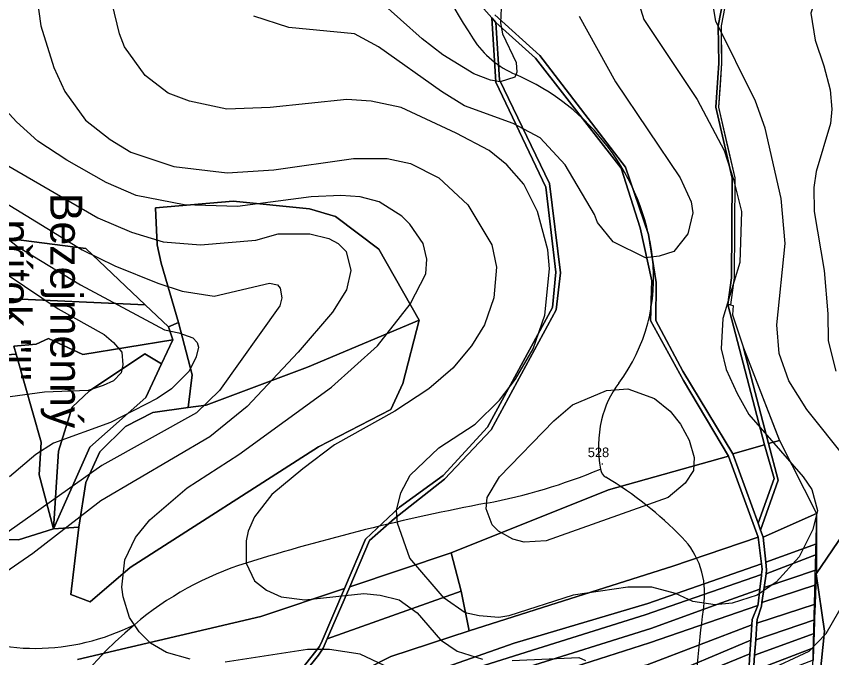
# Model space of a CAD drawing. Extents: x -510989 to -501240, y -1184665 to -1176098.
# Drawn here: x -509271 to -508760, y -1177973 to -1177572 of the extents above; entities that cross this region are included whole.
import ezdxf

# ---------------------------------------------------------------- set-up
doc = ezdxf.new("R2010")
doc.units = 0
for name, color, linetype in [('lesni_pozemek', 7, 'Continuous'), ('NAVRH_rozvodnice', 7, 'Continuous'), ('ostatni_plocha_x_ostatni_komunikace', 7, 'Continuous'), ('popis', 7, 'Continuous'), ('STAV_povodi', 7, 'Continuous'), ('STAV_USES', 7, 'Continuous'), ('vrstevnice_01', 7, 'Continuous'), ('vrstevnice_02', 7, 'Continuous'), ('vrstevnice_05', 7, 'Continuous')]:
    doc.layers.add(name, color=color, linetype=linetype)

msp = doc.modelspace()

# ---------------------------------------------------------------- linework, layer by layer
at = {"layer": 'lesni_pozemek'}
for points in [[(-508825.95, -1177550.04), (-508831.28, -1177577.88), (-508830.98, -1177601.29), (-508832.87, -1177628.86), (-508822.71, -1177673.28), (-508823.1, -1177735.5), (-508825.26, -1177752.3), (-508802.43, -1177839.98), (-508822.23, -1177845.65), (-508853.52, -1177793.89), (-508870.46, -1177762.32), (-508870.1, -1177738.53), (-508874.93, -1177708.45), (-508889.31, -1177666.35), (-508942.96, -1177596.56), (-508971.1, -1177571.13)], [(-508986.2, -1177557.99), (-508973.14, -1177572.9), (-508970.58, -1177613.22), (-508939.21, -1177678.9), (-508933.1, -1177731.98), (-508935.17, -1177754.12), (-508975.79, -1177829.02), (-509003.54, -1177859.28), (-509030.8, -1177879.01), (-509052.19, -1177899.03), (-509065.4, -1177929.91), (-509117.63, -1177947.35), (-509232.41, -1177974.31)], [(-509368.09, -1177896.51), (-509269.43, -1177899.49), (-509247.48, -1177892.47), (-509231.55, -1177891.53), (-509236.62, -1177933.69), (-509224.49, -1177938.17), (-509199.53, -1177916.69), (-509081.59, -1177841.26), (-509036.26, -1177817.95), (-509028.86, -1177801.63), (-509018.6, -1177762.06), (-509043.74, -1177717.55), (-509070.88, -1177697.22), (-509087.17, -1177692.47), (-509134.99, -1177687.6), (-509183.61, -1177691.74), (-509182.52, -1177714.98), (-509180.02, -1177726.39), (-509169.13, -1177763.48), (-509175.54, -1177766.22), (-509190.09, -1177752.44), (-509227.24, -1177717.25), (-509274.16, -1177711.28)], [(-509232.41, -1177974.31), (-509117.63, -1177947.35), (-509065.4, -1177929.91), (-509079.35, -1177962.52), (-509080.85, -1177966.05), (-509100.39, -1177990.69)]]:
    msp.add_lwpolyline(points, dxfattribs=at)
for points in [[(-508945.69, -1177598.23), (-508892.18, -1177666.97), (-508880.3, -1177704.25), (-508872.94, -1177737.37), (-508873.65, -1177762.28), (-508853.05, -1177799.88), (-508825.01, -1177847.03), (-508900.12, -1177868.11), (-508998.54, -1177907.58), (-509062.05, -1177928.79), (-509049.58, -1177899.86), (-509033.96, -1177886.15), (-509002.63, -1177861.51), (-508973.4, -1177830.64), (-508932.81, -1177755.64), (-508930.17, -1177732.36), (-508936.97, -1177676.59), (-508968.33, -1177611.84), (-508970.48, -1177575.95)], [(-509183.61, -1177691.74), (-509134.99, -1177687.6), (-509087.17, -1177692.47), (-509070.88, -1177697.22), (-509043.74, -1177717.55), (-509018.6, -1177762.06), (-509088.47, -1177791.42), (-509151.8, -1177815.23), (-509163.19, -1177816.64), (-509160.59, -1177796.3), (-509169.13, -1177763.48), (-509180.02, -1177726.39), (-509182.52, -1177714.98)], [(-509336.68, -1177703.21), (-509323.78, -1177703.76), (-509296.4, -1177708.45), (-509274.16, -1177711.28), (-509227.24, -1177717.25), (-509190.09, -1177752.44), (-509281.88, -1177748.35), (-509310.14, -1177743.6), (-509369.65, -1177715.71), (-509371.53, -1177713.69), (-509381.06, -1177712.35), (-509377.83, -1177696.33)], [(-509395.4, -1177703.59), (-509381.06, -1177712.35), (-509371.53, -1177713.69), (-509369.65, -1177715.71), (-509346.15, -1177740.87), (-509334.77, -1177760.26), (-509334.42, -1177770.52), (-509317.21, -1177786.73), (-509270.78, -1177783.38), (-509255.22, -1177838.34), (-509256.51, -1177858.83), (-509247.48, -1177892.47), (-509269.43, -1177899.49), (-509368.09, -1177896.51), (-509389.83, -1177840.04), (-509406.67, -1177783.18), (-509415.55, -1177773.21), (-509424.26, -1177763.43), (-509459.96, -1177714.28), (-509460.46, -1177711.83), (-509428.68, -1177701.8)], [(-509369.65, -1177715.71), (-509310.14, -1177743.6), (-509281.88, -1177748.35), (-509190.09, -1177752.44), (-509175.54, -1177766.22), (-509172.83, -1177774.43), (-509229.18, -1177783.49), (-509250.51, -1177773.62), (-509258.36, -1177777.12), (-509272.24, -1177778.21), (-509270.78, -1177783.38), (-509317.21, -1177786.73), (-509334.42, -1177770.52), (-509334.77, -1177760.26), (-509346.15, -1177740.87)], [(-509175.54, -1177766.22), (-509169.13, -1177763.48), (-509160.59, -1177796.3), (-509163.19, -1177816.64), (-509185.34, -1177819.89), (-509202.38, -1177828.64), (-509218.48, -1177844.48), (-509227.2, -1177863.48), (-509231.55, -1177891.53), (-509247.48, -1177892.47), (-509224.81, -1177841.41), (-509189.71, -1177810.48), (-509179.79, -1177789.28), (-509172.83, -1177774.43)], [(-509018.6, -1177762.06), (-509028.86, -1177801.63), (-509036.26, -1177817.95), (-509081.59, -1177841.26), (-509199.53, -1177916.69), (-509224.49, -1177938.17), (-509236.62, -1177933.69), (-509231.55, -1177891.53), (-509227.2, -1177863.48), (-509218.48, -1177844.48), (-509202.38, -1177828.64), (-509185.34, -1177819.89), (-509163.19, -1177816.64), (-509151.8, -1177815.23), (-509088.47, -1177791.42)], [(-509250.51, -1177773.62), (-509229.18, -1177783.49), (-509172.83, -1177774.43), (-509179.79, -1177789.28), (-509190.31, -1177783.11), (-509224.99, -1177806.15), (-509235.83, -1177816.55), (-509244.28, -1177844), (-509247.48, -1177892.47), (-509256.51, -1177858.83), (-509255.22, -1177838.34), (-509270.78, -1177783.38), (-509272.24, -1177778.21), (-509258.36, -1177777.12)], [(-509179.79, -1177789.28), (-509189.71, -1177810.48), (-509224.81, -1177841.41), (-509247.48, -1177892.47), (-509244.28, -1177844), (-509235.83, -1177816.55), (-509224.99, -1177806.15), (-509190.31, -1177783.11)], [(-508793.21, -1177836.93), (-508793.07, -1177837.3), (-508799.81, -1177839.23), (-508815.51, -1177779.25)], [(-508822.23, -1177845.65), (-508802.43, -1177839.98), (-508796.34, -1177861.15), (-508806.32, -1177889.11)], [(-508799.81, -1177839.23), (-508793.07, -1177837.3), (-508769.77, -1177882.88), (-508803.19, -1177897.68), (-508804.78, -1177893.32), (-508793.85, -1177862.2)], [(-508900.12, -1177868.11), (-508825.01, -1177847.03), (-508806.28, -1177897.85), (-508859.67, -1177916), (-508936.67, -1177940.28), (-508987.15, -1177956.38), (-508992.36, -1177931.55), (-508998.54, -1177907.58)], [(-508769.77, -1177882.88), (-508769.75, -1177901.97), (-508801.54, -1177913.34), (-508803.19, -1177897.68)], [(-508806.28, -1177897.85), (-508804.15, -1177914.52), (-508875.38, -1177939.19), (-508959.16, -1177964.08), (-509074.82, -1178004.67), (-509111.08, -1178010.09), (-509105.44, -1178004.14), (-509100.17, -1177995.27), (-509069.33, -1177989.03), (-509036.27, -1177972.5), (-508987.15, -1177956.38), (-508936.67, -1177940.28), (-508859.67, -1177916)], [(-508769.74, -1177908.54), (-508801.39, -1177920.77), (-508801.03, -1177918.21), (-508801.54, -1177913.34), (-508769.75, -1177901.97)], [(-509062.05, -1177928.79), (-508998.54, -1177907.58), (-508992.36, -1177931.55), (-509076.08, -1177961.36)], [(-508769.73, -1177915.4), (-508769.84, -1177918.3), (-508802.6, -1177929.23), (-508801.39, -1177920.77), (-508769.74, -1177908.54)], [(-508804.15, -1177914.52), (-508803.74, -1177917.73), (-508804.17, -1177921.18), (-508877.09, -1177946.41), (-508944.29, -1177967.4), (-508996.73, -1177983.78), (-509067.03, -1178009.67), (-509122.64, -1178022.27), (-509111.08, -1178010.09), (-509074.82, -1178004.67), (-508959.16, -1177964.08), (-508875.38, -1177939.19)], [(-508804.17, -1177921.18), (-508804.25, -1177921.87), (-508805.25, -1177930.11), (-508805.26, -1177930.19), (-508829.2, -1177938.88), (-508873.52, -1177954.94), (-508953.47, -1177979.96), (-508997.15, -1177993.63), (-509067.19, -1178019.01), (-509132.5, -1178033.97), (-509122.64, -1178022.27), (-509067.03, -1178009.67), (-508996.73, -1177983.78), (-508944.29, -1177967.4), (-508877.09, -1177946.41)], [(-508770.19, -1177927.48), (-508803.95, -1177938.64), (-508802.6, -1177929.23), (-508769.84, -1177918.3)], [(-508805.26, -1177930.19), (-508806.39, -1177939.45), (-508806.53, -1177940.6), (-508874.28, -1177963.93), (-508947.4, -1177987.17), (-509067.75, -1178029.97), (-509140.79, -1178046.49), (-509132.5, -1178033.97), (-509067.19, -1178019.01), (-508997.15, -1177993.63), (-508953.47, -1177979.96), (-508873.52, -1177954.94), (-508829.2, -1177938.88)], [(-508992.36, -1177931.55), (-508987.15, -1177956.38), (-509036.27, -1177972.5), (-509069.33, -1177989.03), (-509100.17, -1177995.27), (-509098.68, -1177992.77), (-509081.5, -1177971.66), (-509078.57, -1177967.14), (-509076.08, -1177961.36)], [(-508770.19, -1177927.48), (-508770.66, -1177939.7), (-508807.11, -1177951.6), (-508806.94, -1177949.31), (-508804.28, -1177940.97), (-508803.95, -1177938.64)], [(-508806.53, -1177940.6), (-508810.19, -1177949.32), (-508810.39, -1177952.5), (-508875.87, -1177977.59), (-508905.22, -1177985.17), (-508948.08, -1177999.95), (-508972.48, -1178008.36), (-509011.93, -1178021.39), (-509049.63, -1178034.31), (-509091.67, -1178048.05), (-509121.92, -1178053.59), (-509150.14, -1178060.6), (-509140.79, -1178046.49), (-509067.75, -1178029.97), (-508947.4, -1177987.17), (-508874.28, -1177963.93)], [(-508771, -1177948.51), (-508771.03, -1177949.49), (-508807.88, -1177962.08), (-508807.11, -1177951.6), (-508770.66, -1177939.7)], [(-508810.39, -1177952.5), (-508811, -1177962.29), (-508871.29, -1177987.63), (-508957.53, -1178018.19), (-509020.48, -1178039.36), (-509063.78, -1178053.18), (-509104.98, -1178061.47), (-509106.84, -1178061.13), (-509113.54, -1178057.24), (-509158.14, -1178073.02), (-509150.14, -1178060.6), (-509121.92, -1178053.59), (-509091.67, -1178048.05), (-509049.63, -1178034.31), (-509011.93, -1178021.39), (-508972.48, -1178008.36), (-508948.08, -1177999.95), (-508905.22, -1177985.17), (-508875.87, -1177977.59)], [(-508771.33, -1177958.1), (-508808.59, -1177971.67), (-508807.88, -1177962.08), (-508771.03, -1177949.49)], [(-508811, -1177962.29), (-508811.52, -1177970.69), (-508862.51, -1177991.57), (-508933.29, -1178017.67), (-508989.67, -1178037.82), (-509064.49, -1178061.9), (-509103.58, -1178069.74), (-509104.98, -1178061.47), (-509063.78, -1178053.18), (-509020.48, -1178039.36), (-508957.53, -1178018.19), (-508871.29, -1177987.63)], [(-508771.65, -1177966.97), (-508809.31, -1177981.38), (-508808.59, -1177971.67), (-508771.33, -1177958.1)], [(-508771.93, -1177974.62), (-508810.53, -1177989.45), (-508809.81, -1177988.13), (-508809.31, -1177981.38), (-508771.65, -1177966.97)], [(-508811.52, -1177970.69), (-508812.21, -1177981.68), (-508848.22, -1177996), (-508909.09, -1178019.27), (-508986.62, -1178044.82), (-509029.02, -1178058.79), (-509070.47, -1178071.64), (-509097.96, -1178076.43), (-509103.58, -1178069.74), (-509064.49, -1178061.9), (-508989.67, -1178037.82), (-508933.29, -1178017.67), (-508862.51, -1177991.57)]]:
    msp.add_lwpolyline(points, close=True, dxfattribs=at)
at = {"layer": 'NAVRH_rozvodnice'}
for centre, radius, start, end in [((-508669.12, -1177378.82), 377.62, 199.0374, 213.2975), ((-508934.26, -1177552.97), 60.41, 213.2975, 246.8138), ((-509014.23, -1177739.68), 142.71, 6.916, 66.8138), ((-508981.45, -1177735.71), 109.69, 323.2339, 6.916), ((-508843.49, -1177838.79), 62.53, 143.2339, 166.7507), ((-508831.15, -1177841.7), 75.21, 166.7507, 190.3863), ((-509042.95, -1177523.22), 359.5, 280.6777, 292.5435), ((-508897.85, -1177853.92), 7.4, 190.3863, 238.9815), ((-509024.78, -1178065.01), 238.92, 44.3548, 58.9815), ((-508728.02, -1179193.51), 1340.22, 100.67769, 107.31083), ((-508889.25, -1177932.5), 49.37, 352.4283, 44.3548), ((-509067.08, -1178105.65), 200.74, 107.3108, 130.2783), ((-508055.34, -1178043.34), 791.88, 172.42833, 177.3333), ((-509259.09, -1177829.08), 138.22, 243.7065, 296.7576), ((-509010.14, -1178172.85), 288.82, 130.2783, 180.3281)]:
    msp.add_arc(centre, radius, start, end, dxfattribs=at)
at = {"layer": 'ostatni_plocha_x_ostatni_komunikace'}
for points in [[(-508824.15, -1177549.66), (-508829.58, -1177578.03), (-508829.28, -1177601.34), (-508831.16, -1177628.73), (-508821.01, -1177673.09), (-508821.4, -1177735.61), (-508823.57, -1177752.52), (-508825.26, -1177752.3), (-508823.1, -1177735.5), (-508822.71, -1177673.28), (-508832.87, -1177628.86), (-508830.98, -1177601.29), (-508831.28, -1177577.88), (-508825.95, -1177550.04)], [(-508812.21, -1177981.68), (-508811.52, -1177970.69), (-508811, -1177962.29), (-508810.39, -1177952.5), (-508810.19, -1177949.32), (-508806.53, -1177940.6), (-508806.39, -1177939.45), (-508805.26, -1177930.19), (-508805.25, -1177930.11), (-508804.25, -1177921.87), (-508804.17, -1177921.18), (-508803.74, -1177917.73), (-508804.15, -1177914.52), (-508806.28, -1177897.85), (-508825.01, -1177847.03), (-508853.05, -1177799.88), (-508873.65, -1177762.28), (-508872.94, -1177737.37), (-508880.3, -1177704.25), (-508892.18, -1177666.97), (-508945.69, -1177598.23), (-508970.48, -1177575.95), (-508973.14, -1177572.9), (-508986.2, -1177557.99)], [(-509100.39, -1177990.69), (-509080.85, -1177966.05), (-509079.35, -1177962.52), (-509065.4, -1177929.91), (-509052.19, -1177899.03), (-509030.8, -1177879.01), (-509003.54, -1177859.28), (-508975.79, -1177829.02), (-508935.17, -1177754.12), (-508933.1, -1177731.98), (-508939.21, -1177678.9), (-508970.58, -1177613.22), (-508973.14, -1177572.9), (-508970.48, -1177575.95), (-508968.33, -1177611.84), (-508936.97, -1177676.59), (-508930.17, -1177732.36), (-508932.81, -1177755.64), (-508973.4, -1177830.64), (-509002.63, -1177861.51), (-509033.96, -1177886.15), (-509049.58, -1177899.86), (-509062.05, -1177928.79), (-509076.08, -1177961.36), (-509078.57, -1177967.14), (-509081.5, -1177971.66), (-509098.68, -1177992.77)], [(-508971.1, -1177571.13), (-508942.96, -1177596.56), (-508889.31, -1177666.35), (-508874.93, -1177708.45), (-508870.1, -1177738.53), (-508870.46, -1177762.32), (-508853.52, -1177793.89), (-508822.23, -1177845.65), (-508806.32, -1177889.11), (-508804.78, -1177893.32), (-508803.19, -1177897.68), (-508801.54, -1177913.34), (-508801.03, -1177918.21), (-508801.39, -1177920.77), (-508802.6, -1177929.23), (-508803.95, -1177938.64), (-508804.28, -1177940.97), (-508806.94, -1177949.31), (-508807.11, -1177951.6), (-508807.88, -1177962.08), (-508808.59, -1177971.67), (-508809.31, -1177981.38)]]:
    msp.add_lwpolyline(points, dxfattribs=at)
msp.add_lwpolyline([(-508825.26, -1177752.3), (-508823.57, -1177752.52), (-508821.91, -1177752.81), (-508822.43, -1177758.66), (-508815.51, -1177779.25), (-508799.81, -1177839.23), (-508793.85, -1177862.2), (-508804.78, -1177893.32), (-508806.32, -1177889.11), (-508796.34, -1177861.15), (-508802.43, -1177839.98)], close=True, dxfattribs=at)
at = {"layer": 'popis'}
msp.add_lwpolyline([(-508824.15, -1177549.66), (-508829.58, -1177578.03), (-508829.43, -1177589.69), (-508829.28, -1177601.34), (-508830.22, -1177615.03), (-508831.16, -1177628.73), (-508826.09, -1177650.91), (-508821.01, -1177673.09), (-508821.21, -1177704.35), (-508821.4, -1177735.61), (-508823.57, -1177752.52), (-508821.91, -1177752.81), (-508822.43, -1177758.66), (-508815.51, -1177779.25), (-508793.07, -1177837.3), (-508769.77, -1177882.88), (-508772.69, -1177995.76)], dxfattribs=at)
at = {"layer": 'STAV_povodi'}
for centre, radius, start, end in [((-508669.12, -1177378.82), 377.62, 199.0374, 213.2975), ((-508934.26, -1177552.97), 60.41, 213.2975, 246.8138), ((-509014.23, -1177739.68), 142.71, 6.916, 66.8138), ((-508981.45, -1177735.71), 109.69, 323.2339, 6.916), ((-508843.49, -1177838.79), 62.53, 143.2339, 166.7507), ((-508831.15, -1177841.7), 75.21, 166.7507, 190.3863), ((-508897.85, -1177853.92), 7.4, 190.3863, 238.9815), ((-509024.78, -1178065.01), 238.92, 44.3548, 58.9815), ((-508889.25, -1177932.5), 49.37, 352.4283, 44.3548), ((-508055.34, -1178043.34), 791.88, 172.42833, 177.3333)]:
    msp.add_arc(centre, radius, start, end, dxfattribs=at)
at = {"layer": 'STAV_USES'}
for p, q in [((-508770.08, -1177920.71), (-508753.16, -1177895.94)), ((-508753.16, -1177895.94), (-508770.08, -1177920.71)), ((-508764.8, -1177956.53), (-508770.08, -1177920.71)), ((-508770.08, -1177920.71), (-508764.8, -1177956.53)), ((-508771.19, -1178017.2), (-508764.8, -1177956.53)), ((-508764.8, -1177956.53), (-508771.19, -1178017.2))]:
    msp.add_line(p, q, dxfattribs=at)
at = {"layer": 'vrstevnice_01'}
for points in [[(-508751, -1177519), (-508760.91, -1177542), (-508767.5, -1177553), (-508773.31, -1177570), (-508770.69, -1177587), (-508765.19, -1177603), (-508761.31, -1177618), (-508760.31, -1177630), (-508761.09, -1177639), (-508770.09, -1177669), (-508771.41, -1177679), (-508771.31, -1177694), (-508765, -1177731), (-508762.69, -1177758), (-508762.59, -1177775), (-508757.69, -1177794)], [(-508881.59, -1177562), (-508878, -1177574), (-508844.59, -1177624), (-508827.69, -1177656), (-508821.69, -1177674), (-508816.81, -1177694), (-508817.81, -1177726), (-508828.41, -1177761), (-508829.41, -1177780), (-508826.31, -1177793), (-508819.5, -1177808), (-508812.19, -1177821), (-508778.09, -1177860), (-508772.69, -1177868), (-508769.09, -1177881), (-508772.19, -1177893), (-508780.69, -1177910), (-508795.09, -1177926), (-508806.91, -1177934), (-508822.69, -1177939), (-508833.31, -1177940), (-508847.31, -1177938), (-508858.09, -1177933), (-508873, -1177929), (-508888, -1177929), (-508922.19, -1177934), (-508962.5, -1177947), (-508968.69, -1177948), (-508981.09, -1177947), (-508989.81, -1177945), (-509003, -1177936), (-509024.31, -1177911), (-509032.19, -1177889), (-509032.81, -1177881), (-509030, -1177870), (-509024.19, -1177859), (-509006.31, -1177842), (-508983.41, -1177827), (-508968.31, -1177812), (-508958.31, -1177799), (-508947.19, -1177780), (-508939.91, -1177759), (-508936.91, -1177730), (-508938, -1177718), (-508944.5, -1177694), (-508953, -1177677), (-508963.59, -1177665), (-508974.81, -1177656), (-508995.31, -1177645), (-509029.91, -1177629), (-509048.69, -1177625), (-509063.81, -1177624), (-509111.81, -1177629), (-509139, -1177630), (-509162.41, -1177625), (-509175.69, -1177620), (-509190, -1177609), (-509203, -1177591), (-509206.19, -1177583), (-509210.81, -1177564)], [(-508967.31, -1177567), (-508967.59, -1177576), (-508966.31, -1177583), (-508957.91, -1177601), (-508957.41, -1177607), (-508958.69, -1177610), (-508967.81, -1177613), (-508973.81, -1177612), (-508984.31, -1177608), (-509003.69, -1177596), (-509016.69, -1177586), (-509043.81, -1177562)], [(-509193.81, -1177957), (-509199.91, -1177948), (-509203.91, -1177935), (-509204.69, -1177929), (-509202.91, -1177912), (-509196.09, -1177898), (-509187.09, -1177887), (-509163.81, -1177867), (-509131.41, -1177846), (-509073.5, -1177804), (-509044.59, -1177778), (-509024.19, -1177752), (-509014.41, -1177733), (-509013.69, -1177724), (-509016.09, -1177714), (-509024.31, -1177702), (-509029.41, -1177697), (-509043.69, -1177688), (-509055.59, -1177685), (-509067.69, -1177684), (-509086.09, -1177685), (-509132.31, -1177691), (-509165.69, -1177690), (-509195.69, -1177684), (-509214.5, -1177676), (-509239.09, -1177662), (-509257.19, -1177650), (-509270.59, -1177638), (-509286.59, -1177621)], [(-509293.41, -1177679), (-509229.5, -1177718), (-509209.09, -1177728), (-509182.09, -1177739), (-509167, -1177744), (-509146.81, -1177747), (-509112.31, -1177739), (-509107.31, -1177740), (-509105.5, -1177742), (-509104.59, -1177748), (-509105.81, -1177753), (-509143.59, -1177806), (-509158, -1177820), (-509217.31, -1177853), (-509313.31, -1177921)], [(-509275.91, -1177734), (-509244.5, -1177755), (-509215.69, -1177771), (-509210, -1177776), (-509204.69, -1177782), (-509204.09, -1177790), (-509205.19, -1177795), (-509209.91, -1177800), (-509216.31, -1177803), (-509225.69, -1177806), (-509253.19, -1177807), (-509274.69, -1177810)], [(-509162, -1177974), (-509176.81, -1177970), (-509186.81, -1177964), (-509193.81, -1177957)], [(-509040.41, -1177978), (-509055.59, -1177971), (-509074.59, -1177968), (-509088.41, -1177968), (-509140, -1177976)]]:
    msp.add_lwpolyline(points, dxfattribs=at)
at = {"layer": 'vrstevnice_02'}
for points in [[(-508751, -1177849), (-508775.91, -1177818), (-508787.19, -1177800), (-508793.19, -1177783), (-508794.69, -1177765), (-508789.5, -1177714), (-508792, -1177686), (-508801.91, -1177642), (-508808.09, -1177625), (-508832.91, -1177575), (-508834.81, -1177564), (-508834, -1177557), (-508820.41, -1177537), (-508810.31, -1177526), (-508803.31, -1177516), (-508790.69, -1177492), (-508782.91, -1177472), (-508767.5, -1177402), (-508757.41, -1177380)], [(-509259.5, -1177548), (-509255.31, -1177578), (-509247.31, -1177604), (-509240.31, -1177619), (-509227.5, -1177637), (-509212.09, -1177649), (-509199, -1177657), (-509172.19, -1177666), (-509138.69, -1177670), (-509109.59, -1177668), (-509059.59, -1177661), (-509038.69, -1177661), (-509023.91, -1177664), (-509006.19, -1177673), (-508988, -1177690), (-508973, -1177715), (-508970.19, -1177729), (-508971.91, -1177748), (-508977.59, -1177765), (-508985.69, -1177778), (-508997.5, -1177792), (-509012.41, -1177805), (-509033.81, -1177819), (-509071.5, -1177840), (-509091.31, -1177855), (-509110.69, -1177871), (-509121.69, -1177885), (-509125.69, -1177894), (-509126.91, -1177900), (-509126.81, -1177914), (-509121.69, -1177925), (-509114.19, -1177931), (-509104.91, -1177935), (-509090.19, -1177937), (-509053.09, -1177933), (-509042.91, -1177934), (-509031, -1177937), (-509019.81, -1177945), (-509005.19, -1177962), (-508994.69, -1177969), (-508978.81, -1177974)], [(-508918.31, -1177572), (-508895.59, -1177613), (-508855.09, -1177673), (-508848.19, -1177688), (-508847.31, -1177695), (-508850.41, -1177708), (-508859.09, -1177719), (-508868.31, -1177722), (-508876.81, -1177723), (-508897.19, -1177713), (-508906.91, -1177701), (-508908.81, -1177696), (-508927.09, -1177665), (-508942.81, -1177648), (-508959.69, -1177639), (-508990.09, -1177628), (-509004.59, -1177619), (-509043.91, -1177591), (-509059.09, -1177583), (-509100.19, -1177579), (-509122.09, -1177572)], [(-509276.81, -1177665), (-509219.69, -1177698), (-509198.59, -1177707), (-509178.91, -1177713), (-509155.5, -1177715), (-509120.81, -1177712), (-509106.81, -1177708), (-509086.91, -1177708), (-509075, -1177711), (-509069.19, -1177714), (-509064.31, -1177719), (-509061.41, -1177731), (-509064.09, -1177743), (-509072.91, -1177757), (-509094.31, -1177782), (-509126.31, -1177816), (-509149.69, -1177835), (-509217.81, -1177875), (-509260.31, -1177908), (-509301, -1177936)], [(-509329.09, -1177670), (-509269.91, -1177716), (-509230.5, -1177740), (-509177.91, -1177768), (-509168.91, -1177770), (-509160.31, -1177773), (-509157.5, -1177776), (-509156.69, -1177779), (-509158.19, -1177785), (-509162.59, -1177794), (-509173.5, -1177805), (-509182.5, -1177811), (-509211.81, -1177826), (-509247.41, -1177839), (-509258.59, -1177846), (-509274.91, -1177860)], [(-508934.31, -1177825), (-508922.5, -1177815), (-508901.31, -1177806), (-508888, -1177805), (-508871.31, -1177811), (-508861.5, -1177819), (-508855, -1177827), (-508849.5, -1177837), (-508846.31, -1177848), (-508846.91, -1177856), (-508852, -1177864), (-508862.59, -1177873), (-508939, -1177900), (-508952.91, -1177901), (-508959.91, -1177899), (-508968.81, -1177894), (-508972.81, -1177890), (-508976.69, -1177880), (-508976, -1177873), (-508968.31, -1177860), (-508934.31, -1177825)], [(-508802.09, -1177982), (-508774.5, -1177969), (-508763.69, -1177958), (-508744.81, -1177925)], [(-508960.31, -1177975), (-508918.59, -1177973), (-508914.5, -1177975)]]:
    msp.add_lwpolyline(points, dxfattribs=at)

# ---------------------------------------------------------------- texts
at = {"layer": 'NAVRH_rozvodnice'}
for s, p in [('Bezejmenný', (-509249.48, -1177682.48)), ('přítok "I"', (-509281.48, -1177699.12))]:
    msp.add_text(s, height=20, rotation=270, dxfattribs=at).set_placement(p)
at = {"layer": 'vrstevnice_05'}
for s, p in [('528', (-508913, -1177847.72)), ('.', (-508905.02, -1177852.46))]:
    msp.add_text(s, height=6, dxfattribs=at).set_placement(p)

doc.saveas('drawing.dxf')
